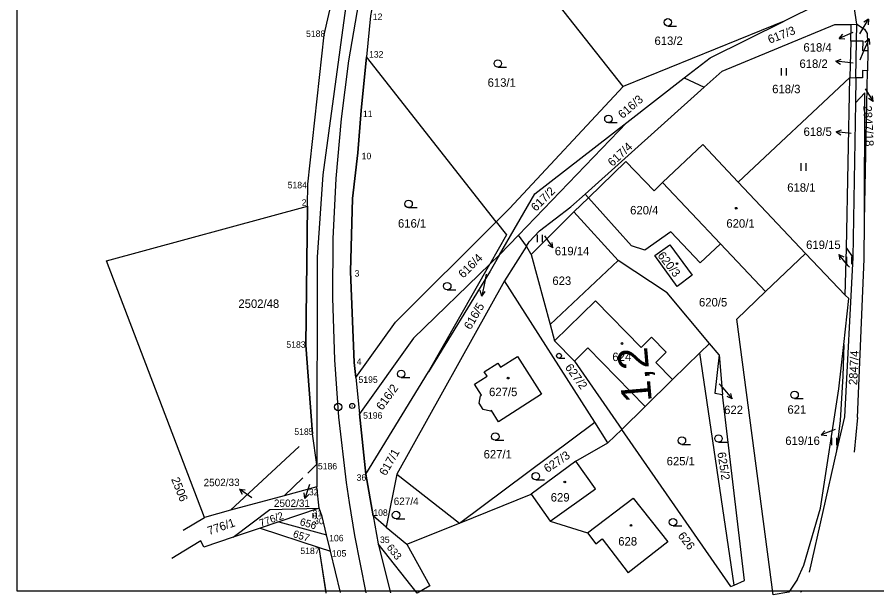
# Model space of a CAD drawing. Extents: x -558358 to -557517, y -1073785 to -1073189.
# Drawn here: x -558357.5 to -558184.5, y -1073784.8 to -1073668.5 of the extents above; entities that cross this region are included whole.
import ezdxf

# ---------------------------------------------------------------- set-up
doc = ezdxf.new("R2010")
doc.units = 0
for name, color, linetype in [('Hranice parcel', 7, 'Continuous'), ('Kolej', 7, 'Continuous'), ('Návěst místo trati', 7, 'Continuous'), ('Parcelní čísla', 7, 'Continuous'), ('Pop  PČ popisy', 7, 'Continuous'), ('Rozpiska_pole_1', 7, 'Continuous'), ('Svazek obcí údolí Desné', 7, 'Continuous'), ('Vnitřní kresba', 7, 'Continuous'), ('Vrstva 60', 7, 'Continuous'), ('Značky budov', 7, 'Continuous'), ('Značky kultur', 7, 'Continuous')]:
    doc.layers.add(name, color=color, linetype=linetype)

msp = doc.modelspace()

# ---------------------------------------------------------------- linework, layer by layer
at = {"layer": 'Hranice parcel'}
for p, q in [((-558235.56, -1073682.51), (-558250.61, -1073663.38)), ((-558188.53, -1073669.97), (-558189.35, -1073664.58)), ((-558196.23, -1073665.95), (-558203.14, -1073669.36)), ((-558203.14, -1073669.36), (-558235.56, -1073682.51)), ((-558189.77, -1073673.37), (-558189.69, -1073669.98)), ((-558189.69, -1073669.98), (-558188.53, -1073669.97)), ((-558188.59, -1073673.36), (-558188.53, -1073669.97)), ((-558188.53, -1073669.97), (-558186.98, -1073670.93)), ((-558189.77, -1073673.37), (-558189.93, -1073680.69)), ((-558188.59, -1073673.36), (-558189.77, -1073673.37)), ((-558188.72, -1073680.72), (-558188.59, -1073673.36)), ((-558187.23, -1073673.34), (-558188.59, -1073673.36)), ((-558186.31, -1073675.34), (-558186.36, -1073679.31)), ((-558261.12, -1073709.7), (-558287.25, -1073676.53)), ((-558234.84, -1073689.73), (-558223.26, -1073680.77)), ((-558223.26, -1073680.77), (-558219.23, -1073682.6)), ((-558189.93, -1073680.69), (-558212.4, -1073701.75)), ((-558190.64, -1073715.05), (-558189.93, -1073680.69)), ((-558189.93, -1073680.69), (-558188.72, -1073680.72)), ((-558188.72, -1073680.72), (-558188.81, -1073685.75)), ((-558187.4, -1073680.75), (-558188.72, -1073680.72)), ((-558187.01, -1073709.55), (-558186.36, -1073679.31)), ((-558243.24, -1073704.13), (-558219.23, -1073682.6)), ((-558186.92, -1073683.79), (-558188.81, -1073685.75)), ((-558187.01, -1073709.55), (-558186.92, -1073683.79)), ((-558188.81, -1073685.75), (-558189.35, -1073716.89)), ((-558256.63, -1073712.41), (-558234.84, -1073689.73)), ((-558227.63, -1073701.8), (-558215.96, -1073714.16)), ((-558212.4, -1073701.75), (-558198.87, -1073716.11)), ((-558245.46, -1073707.69), (-558242.57, -1073704.88)), ((-558242.57, -1073704.88), (-558243.24, -1073704.13)), ((-558233.91, -1073714.56), (-558242.57, -1073704.88)), ((-558339.57, -1073717.56), (-558299.09, -1073706.57)), ((-558245.46, -1073707.69), (-558254.11, -1073716.3)), ((-558236.6, -1073717.53), (-558245.46, -1073707.69)), ((-558256.63, -1073712.41), (-558260.45, -1073716.38)), ((-558255.01, -1073714.6), (-558256.63, -1073712.41)), ((-558255.01, -1073714.6), (-558259.48, -1073721.62)), ((-558254.11, -1073716.3), (-558255.01, -1073714.6)), ((-558206.91, -1073723.76), (-558215.96, -1073714.16)), ((-558190.86, -1073724.46), (-558190.64, -1073715.05)), ((-558190.64, -1073715.05), (-558189.35, -1073716.89)), ((-558262.39, -1073718.25), (-558260.45, -1073716.38)), ((-558254.11, -1073716.3), (-558250.26, -1073730.4)), ((-558198.87, -1073716.11), (-558206.91, -1073723.76)), ((-558190.86, -1073724.46), (-558198.87, -1073716.11)), ((-558319.85, -1073769.2), (-558339.57, -1073717.56)), ((-558274.72, -1073739.9), (-558262.39, -1073718.25)), ((-558250.26, -1073730.4), (-558236.6, -1073717.53)), ((-558226.69, -1073724.03), (-558236.6, -1073717.53)), ((-558259.48, -1073721.62), (-558281.15, -1073760.49)), ((-558241.29, -1073750.06), (-558259.48, -1073721.62)), ((-558218.17, -1073734.19), (-558226.69, -1073724.03)), ((-558250.26, -1073730.4), (-558249.36, -1073733.68)), ((-558220.12, -1073736.1), (-558218.17, -1073734.19)), ((-558216.24, -1073736.49), (-558218.17, -1073734.19)), ((-558191.18, -1073734.38), (-558191.35, -1073740.76)), ((-558213.21, -1073782.82), (-558220.12, -1073736.1)), ((-558216.24, -1073736.49), (-558215.54, -1073744.47)), ((-558287.34, -1073760.54), (-558274.72, -1073739.9)), ((-558191.35, -1073740.76), (-558191.89, -1073749.68)), ((-558191.89, -1073749.68), (-558192.59, -1073755.8)), ((-558188.37, -1073749.08), (-558189.08, -1073756.06)), ((-558268.5, -1073770.34), (-558241.29, -1073750.06)), ((-558238.63, -1073754.22), (-558241.29, -1073750.06)), ((-558235.84, -1073751.49), (-558238.63, -1073754.22)), ((-558213.89, -1073783.12), (-558235.84, -1073751.49)), ((-558300.8, -1073754.92), (-558314.63, -1073767.78)), ((-558245.1, -1073757.92), (-558238.63, -1073754.22)), ((-558192.59, -1073755.8), (-558198.14, -1073780.25)), ((-558245.1, -1073757.92), (-558254.1, -1073764.51)), ((-558300.06, -1073761.28), (-558303.78, -1073764.84)), ((-558281.15, -1073760.49), (-558283.28, -1073771.17)), ((-558281.15, -1073760.49), (-558268.5, -1073770.34)), ((-558297.22, -1073763.06), (-558303.78, -1073764.84)), ((-558303.78, -1073764.84), (-558314.63, -1073767.78)), ((-558268.5, -1073770.34), (-558254.1, -1073764.51)), ((-558254.1, -1073764.51), (-558250.25, -1073769.98)), ((-558314.63, -1073767.78), (-558319.85, -1073769.2)), ((-558296.74, -1073767.33), (-558304.84, -1073770.08)), ((-558283.28, -1073771.17), (-558285.85, -1073768.92)), ((-558324.15, -1073771.75), (-558319.85, -1073769.2)), ((-558304.84, -1073770.08), (-558308.63, -1073771.36)), ((-558304.84, -1073770.08), (-558295.26, -1073772.72)), ((-558279.1, -1073774.62), (-558268.5, -1073770.34)), ((-558250.25, -1073769.98), (-558242.76, -1073772.31)), ((-558308.63, -1073771.36), (-558314.07, -1073773.21)), ((-558308.63, -1073771.36), (-558296.72, -1073775.29)), ((-558283.28, -1073771.17), (-558279.1, -1073774.62)), ((-558314.07, -1073773.21), (-558319.99, -1073775.22)), ((-558323.98, -1073776), (-558326.38, -1073777.46)), ((-558213.89, -1073783.12), (-558213.21, -1073782.82))]:
    msp.add_line(p, q, dxfattribs=at)
for points in [[(-558223.26, -1073680.77), (-558218.03, -1073676.72), (-558203.14, -1073669.36)], [(-558219.23, -1073682.6), (-558215.65, -1073679.39), (-558192.95, -1073670.01), (-558189.69, -1073669.98)], [(-558186.98, -1073670.93), (-558186.43, -1073671.79), (-558186.31, -1073675.34)], [(-558186.31, -1073675.34), (-558187.29, -1073675.33), (-558187.23, -1073673.34)], [(-558186.36, -1073679.31), (-558187.4, -1073679.28), (-558187.4, -1073680.75)], [(-558235.56, -1073682.51), (-558258.46, -1073707.03), (-558261.12, -1073709.7)], [(-558260.45, -1073716.38), (-558253.37, -1073704.07), (-558234.84, -1073689.73)], [(-558227.63, -1073701.8), (-558219.54, -1073694.18), (-558212.4, -1073701.75)], [(-558242.57, -1073704.88), (-558235.04, -1073697.59), (-558229.33, -1073703.46), (-558227.63, -1073701.8)], [(-558255.01, -1073714.6), (-558254.51, -1073713.78), (-558252.39, -1073711.53), (-558246.1, -1073706.69), (-558243.24, -1073704.13)], [(-558289.37, -1073741.07), (-558281.4, -1073729.91), (-558261.12, -1073709.7)], [(-558261.12, -1073709.7), (-558259.03, -1073712.35), (-558262.39, -1073718.25)], [(-558188.37, -1073749.08), (-558187.04, -1073717.25), (-558187.01, -1073709.55)], [(-558215.96, -1073714.16), (-558220.05, -1073717.99), (-558225.94, -1073711.71), (-558231.23, -1073715.41), (-558233.91, -1073714.56)], [(-558224.7, -1073722.72), (-558229.2, -1073716.48), (-558226.19, -1073714.33), (-558221.69, -1073720.48), (-558224.7, -1073722.72)], [(-558260.45, -1073716.38), (-558262.32, -1073719.63), (-558274.72, -1073739.9)], [(-558189.35, -1073716.89), (-558191.03, -1073748.95), (-558192.59, -1073755.8)], [(-558262.39, -1073718.25), (-558277.79, -1073733.11), (-558288.61, -1073748.35)], [(-558200.5, -1073781.61), (-558202.2, -1073784.23), (-558205.35, -1073784.79), (-558212.68, -1073729.29), (-558206.91, -1073723.76)], [(-558191.18, -1073734.38), (-558190.17, -1073725.16), (-558190.86, -1073724.46)], [(-558249.36, -1073733.68), (-558245.38, -1073737.75), (-558235.84, -1073751.49)], [(-558200.5, -1073781.61), (-558199.18, -1073778.85), (-558195.83, -1073767.37), (-558192.17, -1073743.33), (-558191.18, -1073734.38)], [(-558235.84, -1073751.49), (-558231.13, -1073746.88), (-558225.62, -1073741.49), (-558220.12, -1073736.1)], [(-558264.25, -1073744.77), (-558264.05, -1073744.64), (-558265.49, -1073742.37), (-558262.97, -1073740.76), (-558263.51, -1073739.92), (-558260.77, -1073738.16), (-558260.22, -1073739), (-558256.85, -1073736.83), (-558251.99, -1073744.42), (-558260.65, -1073749.95), (-558262.08, -1073747.68), (-558262.29, -1073747.81), (-558263.76, -1073747.5), (-558264.56, -1073746.23), (-558264.25, -1073744.77)], [(-558216.24, -1073736.49), (-558217.14, -1073744.24), (-558215.54, -1073744.47)], [(-558213.21, -1073782.82), (-558211.14, -1073781.9), (-558215.54, -1073744.47)], [(-558250.25, -1073769.98), (-558241.14, -1073763.44), (-558245.1, -1073757.92)], [(-558242.76, -1073772.31), (-558233.55, -1073765.31), (-558226.57, -1073774.11), (-558234.56, -1073780.4)], [(-558314.07, -1073773.21), (-558306.66, -1073767.6), (-558296.74, -1073767.33)], [(-558242.76, -1073772.31), (-558241.08, -1073774.51), (-558239.8, -1073773.53), (-558234.56, -1073780.4)], [(-558319.99, -1073775.22), (-558320.55, -1073773.92), (-558323.98, -1073776)], [(-558279.1, -1073774.62), (-558274.51, -1073783), (-558277.02, -1073784.45), (-558284.85, -1073774.53)]]:
    msp.add_lwpolyline(points, dxfattribs=at)
at = {"layer": 'Kolej'}
msp.add_lwpolyline([(-558287.32, -1073784.41), (-558289.56, -1073772.87), (-558290.66, -1073766.21), (-558291.24, -1073762.21), (-558292.77, -1073749.06), (-558293.62, -1073737.47), (-558294.02, -1073725.05), (-558293.93, -1073713.18), (-558293.34, -1073701.02), (-558292.27, -1073689.01), (-558290.77, -1073677.31), (-558288.8, -1073665.65), (-558286.32, -1073653.74), (-558283.34, -1073641.94), (-558280, -1073630.57), (-558276.23, -1073619.43), (-558271.87, -1073608.04), (-558267.23, -1073597.24), (-558261.98, -1073586.24), (-558256.49, -1073575.8), (-558250.41, -1073565.28), (-558246.06, -1073558.3), (-558241.22, -1073550.9)], dxfattribs=at)
at = {"layer": 'Návěst místo trati'}
msp.add_line((-558290.15, -1073746.78), (-558290.05, -1073746.78), dxfattribs=at)
for centre, radius in [((-558292.92, -1073746.99), 0.75), ((-558290.09, -1073746.78), 0.5)]:
    msp.add_circle(centre, radius, dxfattribs=at)
at = {"layer": 'Pop  PČ popisy'}
for p, q in [((-558187.72, -1073671.53), (-558186.17, -1073668.96)), ((-558186.17, -1073668.96), (-558187.12, -1073669.56)), ((-558186.17, -1073668.96), (-558186.26, -1073670.07)), ((-558189.32, -1073671.65), (-558192.08, -1073672.82)), ((-558192.08, -1073672.82), (-558191.36, -1073671.97)), ((-558187.93, -1073671.89), (-558187.72, -1073671.53)), ((-558192.08, -1073672.82), (-558190.96, -1073672.89)), ((-558187.24, -1073675.66), (-558186.07, -1073672.9)), ((-558186.07, -1073672.9), (-558186.92, -1073673.62)), ((-558186.07, -1073672.9), (-558186, -1073674.02)), ((-558192.74, -1073677.42), (-558191.7, -1073677.02)), ((-558187.86, -1073677.09), (-558187.24, -1073675.66)), ((-558189.76, -1073677.73), (-558192.74, -1073677.42)), ((-558192.74, -1073677.42), (-558191.8, -1073678.02)), ((-558189.29, -1073677.78), (-558189.76, -1073677.73)), ((-558186.84, -1073682.95), (-558185.25, -1073685.5)), ((-558185.25, -1073685.5), (-558186.2, -1073684.91)), ((-558185.25, -1073685.5), (-558185.36, -1073684.38)), ((-558192.66, -1073691.6), (-558191.6, -1073691.23)), ((-558189.68, -1073691.97), (-558192.66, -1073691.6)), ((-558192.66, -1073691.6), (-558191.73, -1073692.22)), ((-558251.41, -1073712.52), (-558249.69, -1073714.98)), ((-558249.69, -1073714.98), (-558250.67, -1073714.45)), ((-558249.69, -1073714.98), (-558249.85, -1073713.87)), ((-558190.25, -1073718.6), (-558192.18, -1073716.3)), ((-558192.18, -1073716.3), (-558191.15, -1073716.75)), ((-558192.18, -1073716.3), (-558191.92, -1073717.39)), ((-558190.03, -1073718.86), (-558190.25, -1073718.6)), ((-558263.11, -1073720.25), (-558263.42, -1073721.72)), ((-558263.42, -1073721.72), (-558264.04, -1073724.66)), ((-558264.04, -1073724.66), (-558264.33, -1073723.57)), ((-558264.04, -1073724.66), (-558263.35, -1073723.78)), ((-558216.21, -1073742.3), (-558215.56, -1073743.06)), ((-558215.56, -1073743.06), (-558213.63, -1073745.36)), ((-558213.63, -1073745.36), (-558213.89, -1073744.27)), ((-558213.63, -1073745.36), (-558214.66, -1073744.91)), ((-558192.9, -1073751.52), (-558195.7, -1073752.59)), ((-558192.88, -1073751.51), (-558192.9, -1073751.52)), ((-558195.7, -1073752.59), (-558194.95, -1073751.77)), ((-558195.7, -1073752.59), (-558194.59, -1073752.7)), ((-558310.33, -1073765.25), (-558312.78, -1073763.52)), ((-558312.78, -1073763.52), (-558311.67, -1073763.69)), ((-558312.78, -1073763.52), (-558312.25, -1073764.51)), ((-558298.67, -1073762.56), (-558299.62, -1073765.4)), ((-558299.62, -1073765.4), (-558299.78, -1073764.29)), ((-558299.62, -1073765.4), (-558298.83, -1073764.61)), ((-558199.56, -1073784.03), (-558199.85, -1073784.27))]:
    msp.add_line(p, q, dxfattribs=at)
at = {"layer": 'Rozpiska_pole_1'}
for p, q in [((-558357.53, -1073784.09), (-558357.53, -1073190.09)), ((-558298.14, -1073752.46), (-558298.07, -1073752.46)), ((-558299.04, -1073760.31), (-558297.22, -1073758.49)), ((-557516.53, -1073784.09), (-558357.53, -1073784.09))]:
    msp.add_line(p, q, dxfattribs=at)
at = {"layer": 'Svazek obcí údolí Desné'}
for p, q in [((-558289.37, -1073741.07), (-558288.61, -1073748.35)), ((-558289.37, -1073741.07), (-558288.61, -1073748.35)), ((-558287.34, -1073760.54), (-558288.61, -1073748.35)), ((-558288.61, -1073748.35), (-558287.34, -1073760.54)), ((-558297.21, -1073758.56), (-558298.08, -1073752.4)), ((-558297.21, -1073758.56), (-558298.08, -1073752.4)), ((-558297.21, -1073758.56), (-558297.22, -1073763.06)), ((-558285.85, -1073768.92), (-558287.34, -1073760.54)), ((-558287.34, -1073760.54), (-558285.85, -1073768.92)), ((-558296.74, -1073767.33), (-558297.22, -1073763.06)), ((-558285.85, -1073768.92), (-558284.85, -1073774.53)), ((-558285.85, -1073768.92), (-558284.85, -1073774.53)), ((-558294.47, -1073776.03), (-558295.26, -1073772.72)), ((-558296.72, -1073775.29), (-558294.47, -1073776.03)), ((-558296.72, -1073775.29), (-558294.47, -1073776.03)), ((-558284.85, -1073774.53), (-558282.4, -1073784.41)), ((-558284.85, -1073774.53), (-558282.4, -1073784.41))]:
    msp.add_line(p, q, dxfattribs=at)
for points in [[(-558237.23, -1073540.41), (-558250.35, -1073559.71), (-558264.4, -1073584.99), (-558277.08, -1073613.49), (-558283.33, -1073632.3), (-558290.3, -1073658.29), (-558296.01, -1073700.28), (-558297.13, -1073716.84), (-558297.21, -1073758.56)], [(-558299.09, -1073706.57), (-558299.03, -1073702.13), (-558295.75, -1073672.1), (-558286.79, -1073633.11)], [(-558299.09, -1073706.57), (-558299.03, -1073702.13), (-558295.75, -1073672.1), (-558286.79, -1073633.11)], [(-558281.64, -1073647.46), (-558284.84, -1073659.61), (-558286.44, -1073668.26), (-558287.25, -1073676.53)], [(-558281.64, -1073647.46), (-558284.84, -1073659.61), (-558286.44, -1073668.26), (-558287.25, -1073676.53)], [(-558289.37, -1073741.07), (-558289.69, -1073738.01), (-558290.44, -1073719.74), (-558290.03, -1073705.01), (-558288.98, -1073695.83), (-558288.33, -1073687.34), (-558287.25, -1073676.53)], [(-558287.25, -1073676.53), (-558288.33, -1073687.34), (-558288.98, -1073695.83), (-558290.03, -1073705.01), (-558290.44, -1073719.74), (-558289.69, -1073738.01), (-558289.37, -1073741.07)], [(-558299.09, -1073706.57), (-558299.44, -1073734.57), (-558298.08, -1073752.4)], [(-558298.08, -1073752.4), (-558299.44, -1073734.57), (-558299.09, -1073706.57)], [(-558295.26, -1073772.72), (-558296.14, -1073769.02), (-558296.74, -1073767.33)], [(-558295.36, -1073784.22), (-558296.72, -1073775.29)], [(-558295.33, -1073784.43), (-558296.72, -1073775.29)], [(-558292.49, -1073784.32), (-558294.47, -1073776.03)]]:
    msp.add_lwpolyline(points, dxfattribs=at)
at = {"layer": 'Vnitřní kresba'}
for p, q in [((-558249.36, -1073733.68), (-558241.14, -1073725.64)), ((-558241.14, -1073725.64), (-558231.97, -1073735)), ((-558231.97, -1073735), (-558229.86, -1073732.94)), ((-558229.86, -1073732.94), (-558226.91, -1073735.96)), ((-558245.38, -1073737.75), (-558242.66, -1073735.09)), ((-558242.66, -1073735.09), (-558231.13, -1073746.88)), ((-558229.02, -1073738.02), (-558226.91, -1073735.96)), ((-558229.02, -1073738.02), (-558225.62, -1073741.49))]:
    msp.add_line(p, q, dxfattribs=at)
at = {"layer": 'Vrstva 60'}
for p, q in [((-558295.75, -1073672.1), (-558295.75, -1073672.1)), ((-558287.25, -1073676.53), (-558287.25, -1073676.53)), ((-558288.33, -1073687.34), (-558288.33, -1073687.34)), ((-558288.98, -1073695.83), (-558288.98, -1073695.83)), ((-558299.03, -1073702.13), (-558299.03, -1073702.13)), ((-558299.09, -1073706.57), (-558299.09, -1073706.57)), ((-558290.44, -1073719.74), (-558290.44, -1073719.74)), ((-558299.44, -1073734.57), (-558299.44, -1073734.57)), ((-558289.69, -1073738.01), (-558289.69, -1073738.01)), ((-558289.37, -1073741.07), (-558289.37, -1073741.07)), ((-558288.61, -1073748.35), (-558288.61, -1073748.35)), ((-558298.08, -1073752.4), (-558298.08, -1073752.4)), ((-558297.21, -1073758.56), (-558297.21, -1073758.56)), ((-558287.34, -1073760.54), (-558287.34, -1073760.54)), ((-558297.22, -1073763.06), (-558297.22, -1073763.06)), ((-558296.74, -1073767.33), (-558296.74, -1073767.33)), ((-558285.85, -1073768.92), (-558285.85, -1073768.92)), ((-558296.14, -1073769.02), (-558296.14, -1073769.02)), ((-558295.26, -1073772.72), (-558295.26, -1073772.72)), ((-558296.72, -1073775.29), (-558296.72, -1073775.29)), ((-558284.85, -1073774.53), (-558284.85, -1073774.53)), ((-558294.47, -1073776.03), (-558294.47, -1073776.03))]:
    msp.add_line(p, q, dxfattribs=at)
at = {"layer": 'Značky budov'}
for centre in [(-558212.8, -1073706.99), (-558224.72, -1073718.13), (-558235.8, -1073734.21), (-558258.73, -1073741.17), (-558247.32, -1073762.08), (-558233.99, -1073770.82)]:
    msp.add_circle(centre, 0.175, dxfattribs=at)
at = {"layer": 'Značky kultur'}
for p, q in [((-558226.57, -1073670.32), (-558224.82, -1073670.32)), ((-558260.8, -1073678.6), (-558259.05, -1073678.6)), ((-558203.68, -1073680.3), (-558203.68, -1073678.8)), ((-558202.68, -1073680.3), (-558202.68, -1073678.8)), ((-558238.53, -1073689.76), (-558236.78, -1073689.76)), ((-558199.75, -1073699.45), (-558199.75, -1073697.95)), ((-558198.75, -1073699.45), (-558198.75, -1073697.95)), ((-558278.75, -1073706.87), (-558277, -1073706.87)), ((-558252.83, -1073713.85), (-558252.83, -1073712.35)), ((-558251.83, -1073713.85), (-558251.83, -1073712.35)), ((-558190.54, -1073718.24), (-558190.54, -1073716.74)), ((-558189.54, -1073718.24), (-558189.54, -1073716.74)), ((-558270.97, -1073723.41), (-558269.22, -1073723.41)), ((-558248.47, -1073737.19), (-558247.3, -1073737.19)), ((-558280.25, -1073741.08), (-558278.5, -1073741.08)), ((-558201.06, -1073745.3), (-558199.31, -1073745.3)), ((-558193.57, -1073754.69), (-558193.57, -1073753.19)), ((-558192.57, -1073754.69), (-558192.57, -1073753.19)), ((-558261.31, -1073753.69), (-558259.56, -1073753.69)), ((-558223.74, -1073754.51), (-558221.99, -1073754.51)), ((-558216.38, -1073754.08), (-558214.63, -1073754.08)), ((-558253.16, -1073761.67), (-558251.41, -1073761.67)), ((-558297.93, -1073769.39), (-558297.93, -1073768.39)), ((-558297.26, -1073769.39), (-558297.26, -1073768.39)), ((-558281.28, -1073769.49), (-558279.53, -1073769.49)), ((-558225.53, -1073770.92), (-558223.78, -1073770.92))]:
    msp.add_line(p, q, dxfattribs=at)
for centre, radius in [((-558226.57, -1073669.57), 0.75), ((-558260.8, -1073677.85), 0.75), ((-558238.53, -1073689.01), 0.75), ((-558278.75, -1073706.12), 0.75), ((-558270.97, -1073722.66), 0.75), ((-558248.48, -1073736.69), 0.502), ((-558280.25, -1073740.33), 0.75), ((-558201.06, -1073744.55), 0.75), ((-558261.3, -1073752.94), 0.75), ((-558223.74, -1073753.76), 0.75), ((-558216.38, -1073753.33), 0.75), ((-558253.16, -1073760.92), 0.75), ((-558281.28, -1073768.74), 0.75), ((-558225.53, -1073770.17), 0.75)]:
    msp.add_circle(centre, radius, dxfattribs=at)

# ---------------------------------------------------------------- texts
at = {"layer": 'Návěst místo trati'}
msp.add_text('1,2', height=6, rotation=95.054, dxfattribs=at).set_placement((-558229.78, -1073745.86))
at = {"layer": 'Parcelní čísla'}
for s, height, rotation, p in [('617/3', 1.7, 21, (-558206.06, -1073673.9)), ('616/3', 1.7, 41, (-558235.68, -1073689.06)), ('2847/18', 1.7, 273, (-558187.23, -1073686.37)), ('617/4', 1.7, 43, (-558237.71, -1073698.7)), ('617/2', 1.7, 45, (-558253.11, -1073707.74)), ('616/4', 1.7, 45, (-558267.74, -1073721.18)), ('620/3', 1.7, 308, (-558228.73, -1073716.55)), ('616/5', 1.7, 60, (-558266.27, -1073731.57)), ('2847/4', 1.7, 87, (-558188.48, -1073742.63)), ('627/2', 1.7, 306, (-558247.35, -1073739.04)), ('616/2', 1.7, 54, (-558284.06, -1073747.79)), ('617/1', 1.7, 60, (-558283.33, -1073760.96)), ('627/3', 1.7, 34, (-558250.81, -1073760.3)), ('625/2', 1.7, 279, (-558216.61, -1073756.19)), ('2506', 1.7, 292, (-558326.57, -1073761.52)), ('2502/33', 1.5, 0.4465, (-558320.01, -1073762.95)), ('776/2', 1.5, 20, (-558308.48, -1073771.15)), ('776/1', 1.7, 18.8548, (-558318.91, -1073772.79)), ('656', 1.5, 344, (-558300.76, -1073770.72)), ('657', 1.5, 342, (-558302.15, -1073773.13)), ('626', 1.7, 308, (-558224.66, -1073772.94)), ('633', 1.5, 308, (-558283.26, -1073775.29))]:
    msp.add_text(s, height=height, rotation=rotation, dxfattribs=at).set_placement(p)
for s, height, p in [('613/2', 1.7, (-558229.26, -1073674.14)), ('618/4', 1.7, (-558199.28, -1073675.47)), ('618/2', 1.7, (-558200.08, -1073678.75)), ('613/1', 1.7, (-558262.85, -1073682.54)), ('618/3', 1.7, (-558205.57, -1073683.84)), ('618/5', 1.7, (-558199.26, -1073692.43)), ('618/1', 1.7, (-558202.54, -1073703.67)), ('620/4', 1.7, (-558234.16, -1073708.23)), ('616/1', 1.7, (-558280.89, -1073710.89)), ('620/1', 1.7, (-558214.79, -1073710.9)), ('619/15', 1.7, (-558198.74, -1073715.19)), ('619/14', 1.7, (-558249.32, -1073716.46)), ('623', 1.7, (-558249.81, -1073722.43)), ('2502/48', 1.7, (-558313.01, -1073727.05)), ('620/5', 1.7, (-558220.3, -1073726.76)), ('624', 1.7, (-558237.74, -1073737.75)), ('627/5', 1.7, (-558262.55, -1073744.81)), ('622', 1.7, (-558215.24, -1073748.41)), ('621', 1.7, (-558202.5, -1073748.34)), ('619/16', 1.7, (-558202.93, -1073754.63)), ('627/1', 1.7, (-558263.65, -1073757.35)), ('625/1', 1.7, (-558226.81, -1073758.74)), ('2502/31', 1.5, (-558305.86, -1073767.11)), ('627/4', 1.5, (-558281.75, -1073766.72)), ('629', 1.7, (-558250.14, -1073766.02)), ('628', 1.7, (-558236.55, -1073774.87))]:
    msp.add_text(s, height=height, dxfattribs=at).set_placement(p)
at = {"layer": 'Vrstva 60'}
for s, p in [('12', (-558285.95, -1073669.1)), ('5188', (-558299.39, -1073672.52)), ('132', (-558286.72, -1073676.67)), ('11', (-558287.94, -1073688.64)), ('10', (-558288.2, -1073697.13)), ('5184', (-558303.09, -1073702.97)), ('2', (-558300.26, -1073706.5)), ('3', (-558289.63, -1073720.74)), ('5183', (-558303.35, -1073735.08)), ('4', (-558289.21, -1073738.52)), ('5195', (-558288.84, -1073742.13)), ('5196', (-558287.9, -1073749.35)), ('5185', (-558301.75, -1073752.61)), ('5186', (-558297.01, -1073759.56)), ('36', (-558289.21, -1073761.84)), ('32', (-558298.82, -1073764.76)), ('31', (-558298.08, -1073769.01)), ('108', (-558285.85, -1073768.9)), ('30', (-558297.77, -1073770.58)), ('106', (-558294.74, -1073774.02)), ('35', (-558284.51, -1073774.36)), ('5187', (-558300.54, -1073776.59)), ('105', (-558294.19, -1073777.1))]:
    msp.add_text(s, height=1.3, dxfattribs=at).set_placement(p)

doc.saveas('drawing.dxf')
